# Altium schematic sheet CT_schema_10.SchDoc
size 287 x 160 mm
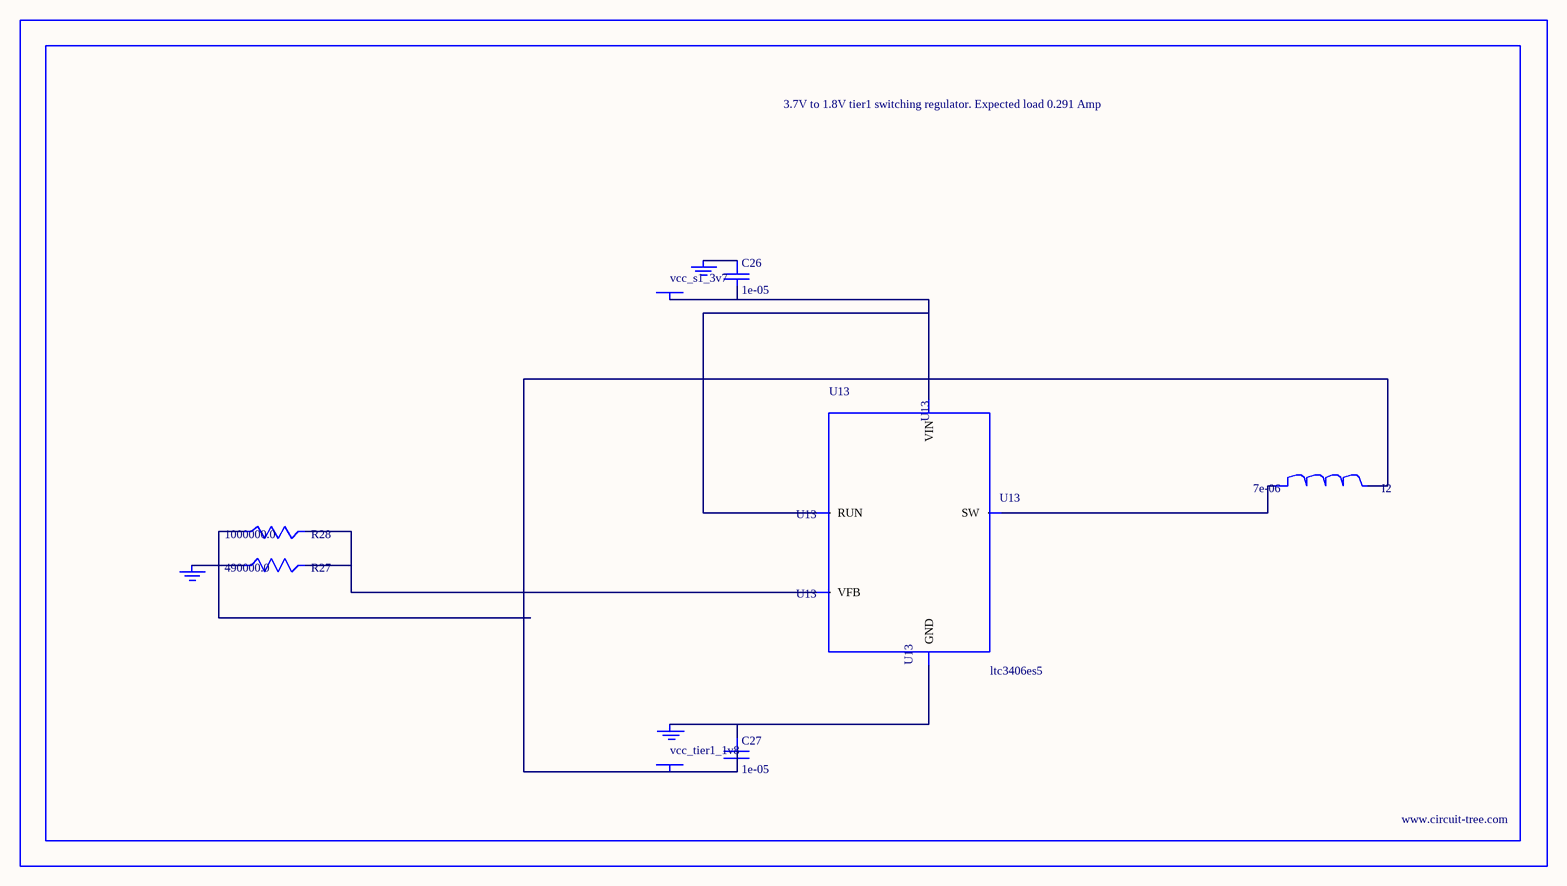
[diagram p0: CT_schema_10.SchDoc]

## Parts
BORDER9  (no value)
C26  1e-05  [C0805]
C27  1e-05  [C0805]
GND_INSTANCE_9_0  (no value)
GND_INSTANCE_9_1  (no value)
GND_INSTANCE_9_2  (no value)
I2  7e-06  [DR1040]
POWER_INSTANCE_9_0  vcc_tier1_1v8
POWER_INSTANCE_9_1  vcc_s1_3v7
R27  490000.0  [R0603]
R28  1000000.0  [R0603]
U13  ltc3406es5  [TSOT-23-5]

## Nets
NetC26_1: C26.1 GND_INSTANCE_9_1.0(GND)
NetC26_2: C26.2 POWER_INSTANCE_9_1.0(PWR) U13.1(RUN) U13.4(VIN)
NetC27_1: C27.1 GND_INSTANCE_9_0.0(GND) U13.2(GND)
NetC27_2: C27.2 I2.2 POWER_INSTANCE_9_0.0(PWR) R28.1
NetGND_INSTANCE_9_2_0: GND_INSTANCE_9_2.0(GND) R27.1
NetI2_1: I2.1 U13.3(SW)
NetR27_2: R27.2 R28.2 U13.5(VFB)

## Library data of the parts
BORDER9 = BORDER_PAGE9
C26 C27 = C0805C106K8RACTU
GND_INSTANCE_9_0-GND_INSTANCE_9_2 = GND
I2 = DR1040-7R0-R
POWER_INSTANCE_9_0 POWER_INSTANCE_9_1 = PWR
R27 = R27
R28 = RC0603JR-071ML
